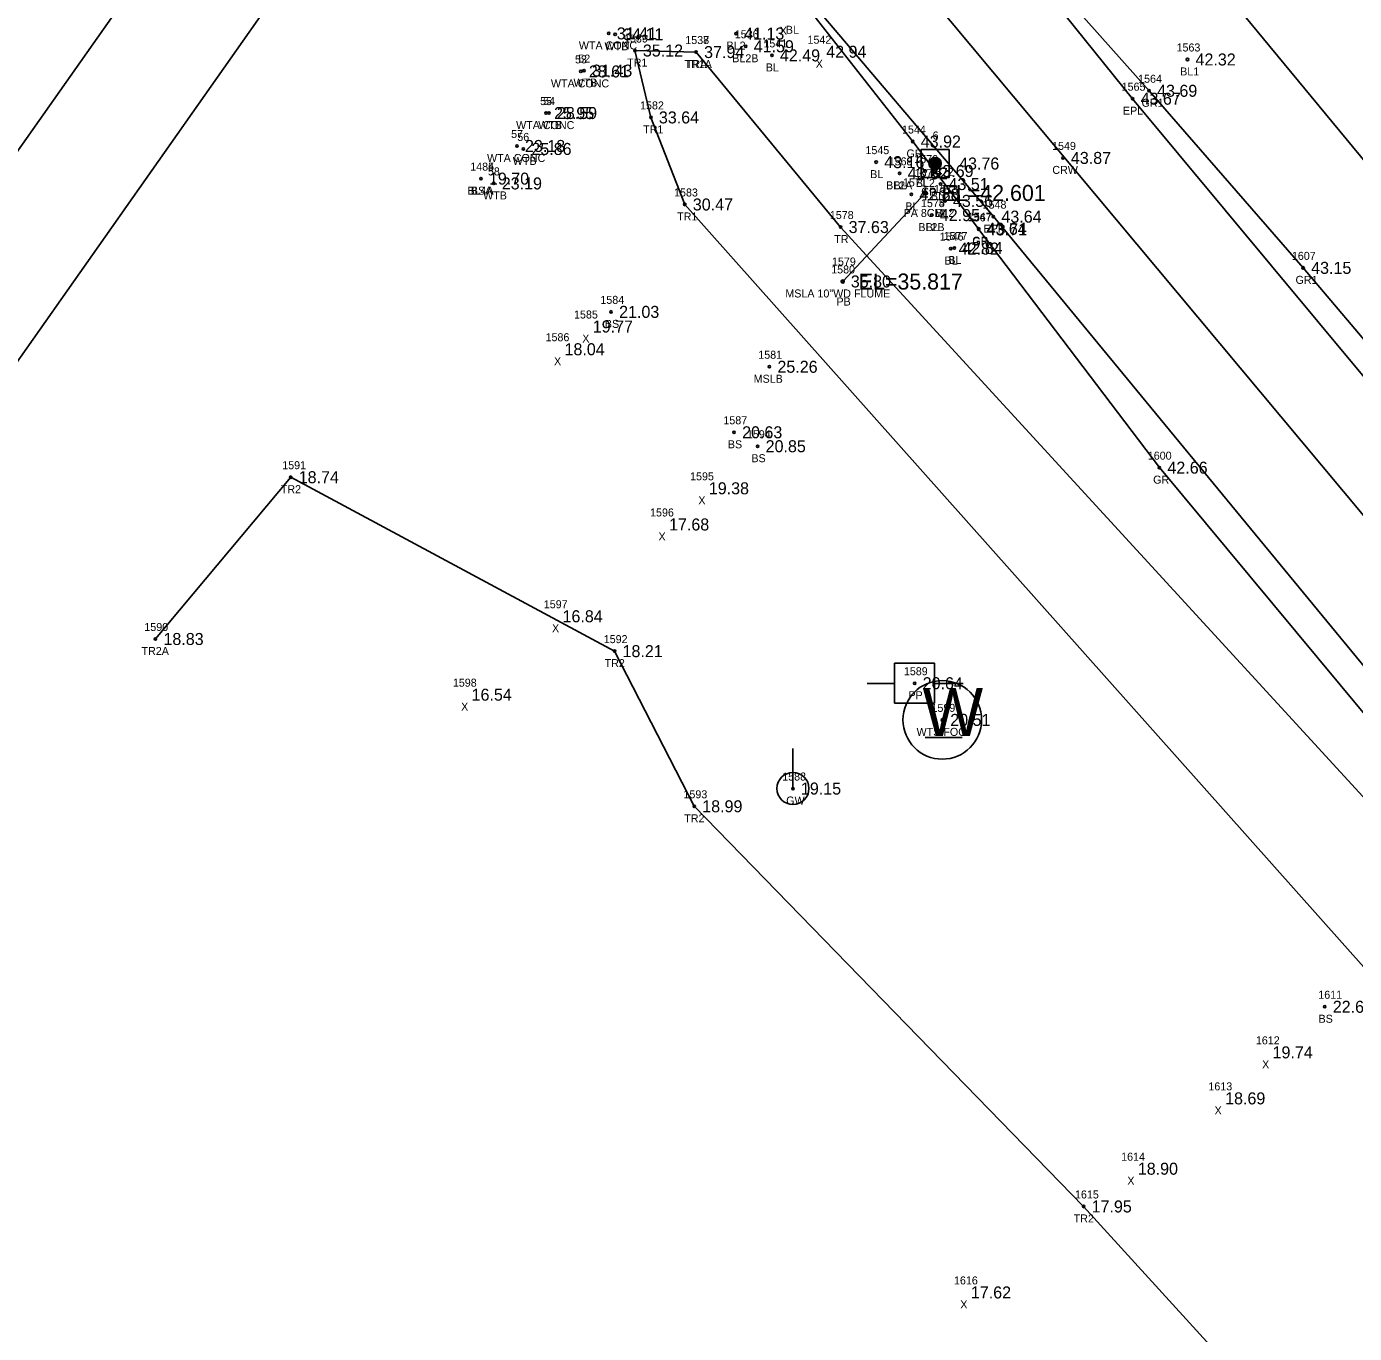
# Model space of a CAD drawing. Extents: x 2042117 to 2045853, y 303080 to 309569.
# Drawn here: x 2043426.9 to 2043592.8, y 305650.3 to 305813.6 of the extents above; entities that cross this region are included whole.
import ezdxf

# ---------------------------------------------------------------- set-up
doc = ezdxf.new("R2010")
doc.units = 0
for name, color, linetype in [('RD_DTM_BkLn_txCode', 7, 'Continuous'), ('RD_EX_DR_Pipe', 7, 'Continuous'), ('RD_EX_DR_Pipe_txCode', 7, 'Continuous'), ('RD_EX_GuardRail', 7, 'Continuous'), ('RD_EX_GuardRail_txCode', 7, 'Continuous'), ('RD_EX_Misc_txCode', 7, 'Continuous'), ('RD_EX_RailRoad', 7, 'Continuous'), ('RD_EX_Road', 7, 'Continuous'), ('RD_EX_Road_txCode', 7, 'Continuous'), ('RD_EX_TX_GuardRail_ELEV', 7, 'Continuous'), ('RD_EX_TX_Misc_ELEV', 7, 'Continuous'), ('RD_EX_TX_Road_ELEV', 7, 'Continuous'), ('RD_EX_TX_UT_ELEV', 7, 'Continuous'), ('RD_EX_TX_VEG_ELEV', 7, 'Continuous'), ('RD_EX_UT', 7, 'Continuous'), ('RD_EX_UT_txCode', 7, 'Continuous'), ('RD_EX_VEG', 7, 'Continuous'), ('RD_EX_VEG_txCode', 7, 'Continuous'), ('RD_HC_Cl', 7, 'Continuous'), ('RD_HC_Survey', 7, 'Continuous'), ('RD_HC_Survey_ELEV', 7, 'Continuous'), ('RD_HC_Survey_txCode', 7, 'Continuous'), ('RD_SMD_Locator', 7, 'Continuous'), ('RD_TX_Pipe_ElevEX', 7, 'Continuous')]:
    doc.layers.add(name, color=color, linetype=linetype)

msp = doc.modelspace()

# ---------------------------------------------------------------- linework, layer by layer
at = {"layer": 'RD_EX_DR_Pipe'}
msp.add_line((2043539.19, 305792.81), (2043528.84, 305781.74), dxfattribs=at)
at = {"layer": 'RD_EX_GuardRail'}
for points in [[(2043536.57, 305840.53), (2043552.74, 305821.73), (2043567.12, 305805.58), (2043586.37, 305783.45), (2043631.29, 305730.39), (2043695.95, 305653.5), (2043733.01, 305610.16)], [(2043521.57, 305819.7), (2043537.59, 305799.24), (2043545.81, 305788.34), (2043545.84, 305788.25), (2043568.41, 305758.48), (2043608.02, 305710.85), (2043672.21, 305633.93), (2043713.59, 305584.16)]]:
    msp.add_lwpolyline(points, dxfattribs=at)
at = {"layer": 'RD_EX_RailRoad'}
for points in [[(2043364.31, 305710.83), (2043487.58, 305885.88), (2043596.31, 306040.36)], [(2043376.84, 305702.3), (2043499.95, 305877.29), (2043608.72, 306031.56)]]:
    msp.add_lwpolyline(points, dxfattribs=at)
at = {"layer": 'RD_EX_Road'}
for points in [[(2043536.39, 305840.18), (2043565.06, 305804.59), (2043628.71, 305728.05), (2043693.07, 305651.37)], [(2043522.11, 305820), (2043547.67, 305789.85), (2043610.72, 305713.32), (2043674.95, 305636.32), (2043738.18, 305559.62), (2043802.42, 305482.71), (2043865.72, 305405.84), (2043929.53, 305328.85), (2043994.13, 305253.28), (2044057.4, 305176.5), (2044121.27, 305100.2), (2044185.29, 305023.54), (2044249.56, 304947.28), (2044313.31, 304870.31), (2044377.09, 304793.29), (2044442, 304716.26), (2044505.92, 304639.55), (2044570.44, 304562.35), (2044634.61, 304485.93), (2044698.46, 304409.27), (2044762.46, 304332.37)]]:
    msp.add_lwpolyline(points, dxfattribs=at)
at = {"layer": 'RD_EX_UT'}
for p, q in [((2043540.32, 305734.05), (2043535.32, 305734.05)), ((2043535.32, 305734.05), (2043535.32, 305729.05)), ((2043540.32, 305729.05), (2043540.32, 305734.05)), ((2043531.89, 305731.49), (2043535.36, 305731.49)), ((2043540.25, 305731.49), (2043543.89, 305731.49)), ((2043535.32, 305729.05), (2043540.32, 305729.05)), ((2043539.15, 305724.75), (2043543.78, 305724.75)), ((2043522.62, 305718.38), (2043522.62, 305723.38))]:
    msp.add_line(p, q, dxfattribs=at)
for centre, radius in [((2043541.28, 305726.96), 4.91), ((2043522.62, 305718.38), 2)]:
    msp.add_circle(centre, radius, dxfattribs=at)
at = {"layer": 'RD_EX_VEG'}
for points in [[(2043547.51, 305881.5), (2043539.7, 305861.32), (2043541.74, 305855.07), (2043567.73, 305828.7), (2043642.4, 305738.29), (2043706.88, 305661.84), (2043768.33, 305586.86), (2043834.29, 305506.38), (2043895.63, 305432.16), (2043964.52, 305353.99), (2044012.41, 305288.23), (2044020.96, 305286.08), (2044026.64, 305287.13), (2044039.88, 305282.36)], [(2043510.52, 305810.42), (2043502.87, 305810.61), (2043504.87, 305802.25), (2043509.11, 305791.37), (2043594.27, 305695.69), (2043658.16, 305620.89), (2043717.86, 305542.89), (2043784.35, 305466.31), (2043848.97, 305392.37), (2043916.01, 305316.79), (2043971.98, 305240.84)], [(2043510.52, 305810.42), (2043528.58, 305788.55), (2043603.52, 305706.8), (2043669.11, 305631.48), (2043746.08, 305529.27), (2043781.83, 305496.01), (2043793.11, 305482.33), (2043857.16, 305399.04), (2043922.61, 305323.93), (2043978.69, 305250.66), (2043978.39, 305246.16), (2043971.98, 305240.84)], [(2043442.97, 305737.07), (2043459.87, 305757.29), (2043500.33, 305735.55), (2043510.29, 305716.16), (2043558.94, 305666.15), (2043625.65, 305592.92), (2043688.91, 305518.94), (2043753.11, 305437.19), (2043818.03, 305364.7), (2043877.83, 305282.82), (2043938.63, 305211.62), (2044011.48, 305138.99), (2044075.86, 305057.44), (2044138.75, 304984.38), (2044203.27, 304905.13), (2044266.06, 304829.27), (2044328.58, 304748.23), (2044394.11, 304672.51), (2044456.79, 304595.02), (2044489.64, 304560.38)]]:
    msp.add_lwpolyline(points, dxfattribs=at)
at = {"layer": 'RD_HC_Cl'}
msp.add_line((2043284.3, 306123.24), (2045221.31, 303804), dxfattribs=at)
at = {"layer": 'RD_HC_Survey'}
for p, q in [((2043539.75, 305796.04), (2043539.75, 305796.94)), ((2043539.78, 305796.01), (2043539.78, 305796.97)), ((2043539.8, 305795.98), (2043539.8, 305797)), ((2043539.82, 305795.95), (2043539.82, 305797.03)), ((2043539.85, 305795.93), (2043539.85, 305797.05)), ((2043539.87, 305795.9), (2043539.87, 305797.07)), ((2043539.9, 305795.88), (2043539.9, 305797.09)), ((2043539.92, 305795.87), (2043539.92, 305797.11)), ((2043539.95, 305795.85), (2043539.95, 305797.13)), ((2043539.97, 305795.83), (2043539.97, 305797.15)), ((2043540, 305795.82), (2043540, 305797.16)), ((2043540.02, 305795.81), (2043540.02, 305797.17)), ((2043540.05, 305795.79), (2043540.05, 305797.19)), ((2043540.07, 305795.78), (2043540.07, 305797.2)), ((2043540.1, 305795.77), (2043540.1, 305797.21)), ((2043540.12, 305795.76), (2043540.12, 305797.22)), ((2043540.15, 305795.75), (2043540.15, 305797.22)), ((2043540.17, 305795.75), (2043540.17, 305797.23)), ((2043540.2, 305795.74), (2043540.2, 305797.24)), ((2043540.22, 305795.74), (2043540.22, 305797.24)), ((2043540.25, 305795.73), (2043540.25, 305797.25)), ((2043540.27, 305795.73), (2043540.27, 305797.25)), ((2043540.29, 305795.72), (2043540.29, 305797.25)), ((2043540.32, 305795.72), (2043540.32, 305797.26)), ((2043540.34, 305795.72), (2043540.34, 305797.26)), ((2043540.37, 305795.72), (2043540.37, 305797.26)), ((2043540.39, 305795.72), (2043540.39, 305797.26)), ((2043540.42, 305795.72), (2043540.42, 305797.26)), ((2043540.44, 305795.72), (2043540.44, 305797.26)), ((2043540.47, 305795.73), (2043540.47, 305797.25)), ((2043540.49, 305795.73), (2043540.49, 305797.25)), ((2043540.52, 305795.73), (2043540.52, 305797.25)), ((2043540.54, 305795.74), (2043540.54, 305797.24)), ((2043540.57, 305795.74), (2043540.57, 305797.23)), ((2043540.59, 305795.75), (2043540.59, 305797.23)), ((2043540.62, 305795.76), (2043540.62, 305797.22)), ((2043540.64, 305795.77), (2043540.64, 305797.21)), ((2043540.67, 305795.78), (2043540.67, 305797.2)), ((2043540.69, 305795.79), (2043540.69, 305797.19)), ((2043540.72, 305795.8), (2043540.72, 305797.18)), ((2043540.74, 305795.81), (2043540.74, 305797.17)), ((2043540.77, 305795.83), (2043540.77, 305797.15)), ((2043540.79, 305795.84), (2043540.79, 305797.14)), ((2043540.81, 305795.86), (2043540.81, 305797.12)), ((2043540.84, 305795.88), (2043540.84, 305797.1)), ((2043540.86, 305795.9), (2043540.86, 305797.08)), ((2043540.89, 305795.92), (2043540.89, 305797.06)), ((2043540.91, 305795.94), (2043540.91, 305797.04)), ((2043540.94, 305795.96), (2043540.94, 305797.01)), ((2043540.96, 305795.99), (2043540.96, 305796.99)), ((2043540.99, 305796.02), (2043540.99, 305796.95)), ((2043539.63, 305796.31), (2043539.63, 305796.67)), ((2043539.65, 305796.23), (2043539.65, 305796.75)), ((2043539.68, 305796.17), (2043539.68, 305796.81)), ((2043539.7, 305796.12), (2043539.7, 305796.86)), ((2043539.73, 305796.08), (2043539.73, 305796.9)), ((2043541.01, 305796.06), (2043541.01, 305796.92)), ((2043541.04, 305796.1), (2043541.04, 305796.88)), ((2043541.06, 305796.14), (2043541.06, 305796.84)), ((2043541.09, 305796.2), (2043541.09, 305796.78)), ((2043541.11, 305796.27), (2043541.11, 305796.71)), ((2043541.14, 305796.38), (2043541.14, 305796.6))]:
    msp.add_line(p, q, dxfattribs=at)
msp.add_lwpolyline([(2043542.12, 305798.24), (2043538.63, 305798.24), (2043538.63, 305794.74), (2043542.12, 305794.74)], close=True, dxfattribs=at)
msp.add_circle((2043540.38, 305796.49), 0.769, dxfattribs=at)
at = {"layer": 'RD_SMD_Locator'}
for centre, radius in [((2043499.61, 305812.75), 0.15), ((2043500.41, 305812.63), 0.15), ((2043515.52, 305812.73), 0.15), ((2043502.87, 305810.61), 0.15), ((2043510.52, 305810.42), 0.15), ((2043510.52, 305810.42), 0.15), ((2043516.72, 305811.14), 0.15), ((2043519.99, 305810), 0.15), ((2043571.92, 305809.49), 0.15), ((2043496.12, 305808), 0.15), ((2043496.53, 305808.1), 0.15), ((2043567.12, 305805.58), 0.15), ((2043565.06, 305804.59), 0.15), ((2043491.77, 305802.79), 0.15), ((2043492.13, 305802.8), 0.15), ((2043504.87, 305802.25), 0.15), ((2043488.14, 305798.68), 0.15), ((2043537.59, 305799.24), 0.15), ((2043488.94, 305798.31), 0.15), ((2043556.35, 305797.19), 0.15), ((2043533.02, 305796.66), 0.15), ((2043535.95, 305795.26), 0.15), ((2043535.95, 305795.26), 0.15), ((2043539.17, 305795.55), 0.15), ((2043540.38, 305796.49), 0.15), ((2043483.64, 305794.6), 0.15), ((2043483.64, 305794.6), 0.15), ((2043485.24, 305794), 0.15), ((2043541.06, 305793.92), 0.15), ((2043537.42, 305792.63), 0.15), ((2043539.19, 305792.81), 0.2), ((2043541.61, 305791.82), 0.15), ((2043509.11, 305791.37), 0.15), ((2043528.58, 305788.55), 0.15), ((2043539.97, 305790.04), 0.15), ((2043539.97, 305790.04), 0.15), ((2043547.67, 305789.85), 0.15), ((2043545.81, 305788.34), 0.15), ((2043545.84, 305788.25), 0.15), ((2043542.33, 305785.86), 0.15), ((2043542.8, 305785.93), 0.15), ((2043586.37, 305783.45), 0.15), ((2043528.84, 305781.74), 0.2), ((2043528.85, 305781.75), 0.15), ((2043499.9, 305777.95), 0.15), ((2043519.68, 305771.09), 0.15), ((2043515.27, 305762.9), 0.15), ((2043518.21, 305761.16), 0.15), ((2043459.87, 305757.29), 0.15), ((2043568.41, 305758.48), 0.15), ((2043442.97, 305737.07), 0.15), ((2043500.33, 305735.55), 0.15), ((2043537.83, 305731.54), 0.15), ((2043541.28, 305726.96), 0.15), ((2043522.62, 305718.38), 0.15), ((2043510.29, 305716.16), 0.15), ((2043589.07, 305691.11), 0.15), ((2043558.94, 305666.15), 0.15)]:
    msp.add_circle(centre, radius, dxfattribs=at)

# ---------------------------------------------------------------- texts
at = {"layer": 'RD_DTM_BkLn_txCode'}
for s, p in [('BL', (2043521.73, 305812.7)), ('1536', (2043515.35, 305812.14)), ('1541', (2043518.93, 305811)), ('BL2', (2043514.32, 305810.73)), ('1563', (2043570.55, 305810.49)), ('BL2B', (2043515.04, 305809.14)), ('BL', (2043519.23, 305808)), ('BL1', (2043571, 305807.49)), ('1545', (2043531.68, 305797.66)), ('1568', (2043534.58, 305796.26)), ('1569', (2043534.58, 305796.26)), ('1570', (2043537.78, 305796.55)), ('1484', (2043482.3, 305795.6)), ('1485', (2043482.3, 305795.6)), ('BL', (2043532.27, 305794.66)), ('1572', (2043539.71, 305794.92)), ('BSA', (2043482.38, 305792.6)), ('BL2A', (2043534.26, 305793.26)), ('BL', (2043535.2, 305793.26)), ('1571', (2043536.36, 305793.63)), ('BL2', (2043537.97, 305793.55)), ('1573', (2043540.26, 305792.82)), ('BL4A', (2043481.95, 305792.6)), ('1574', (2043538.62, 305791.04)), ('1575', (2043538.62, 305791.04)), ('BL2', (2043539.85, 305791.92)), ('BL', (2043536.67, 305790.63)), ('BL2', (2043540.4, 305789.82)), ('BL2B', (2043538.29, 305788.04)), ('BL', (2043539.22, 305788.04)), ('1546', (2043540.96, 305786.86)), ('1577', (2043541.45, 305786.93)), ('BL', (2043541.57, 305783.86)), ('BL', (2043542.04, 305783.93)), ('1584', (2043498.56, 305778.95)), ('BS', (2043499.12, 305775.95)), ('1587', (2043513.93, 305763.9)), ('1594', (2043516.87, 305762.16)), ('BS', (2043514.49, 305760.9)), ('BS', (2043517.43, 305759.16)), ('1611', (2043588.26, 305692.11)), ('BS', (2043588.29, 305689.11))]:
    msp.add_text(s, height=1, dxfattribs=at).set_placement(p)
at = {"layer": 'RD_EX_DR_Pipe_txCode'}
for s, p in [('1576', (2043537.82, 305794.81)), ('PA 8CM', (2043536.45, 305789.81)), ('1579', (2043527.5, 305783.74)), ('PB', (2043528.06, 305778.74))]:
    msp.add_text(s, height=1, dxfattribs=at).set_placement(p)
at = {"layer": 'RD_EX_GuardRail_txCode'}
for s, p in [('1564', (2043565.75, 305806.58)), ('GR1', (2043566.18, 305803.58)), ('1544', (2043536.25, 305800.24)), ('GR', (2043536.81, 305797.24)), ('1547', (2043544.47, 305789.34)), ('1567', (2043544.47, 305789.25)), ('GR', (2043545.03, 305786.34)), ('GR', (2043545.06, 305786.25)), ('1607', (2043584.96, 305784.45)), ('GR1', (2043585.42, 305781.45)), ('1600', (2043566.96, 305759.48)), ('GR', (2043567.63, 305756.48))]:
    msp.add_text(s, height=1, dxfattribs=at).set_placement(p)
at = {"layer": 'RD_EX_Misc_txCode'}
for s, p in [('X', (2043520.98, 305812.59)), ('1542', (2043524.44, 305811.46)), ('WTA CONC', (2043495.87, 305810.75)), ('WTB', (2043499.08, 305810.63)), ('53', (2043495.39, 305809)), ('52', (2043495.8, 305809.1)), ('X', (2043525.47, 305808.46)), ('WTA CONC', (2043492.38, 305806)), ('WTB', (2043495.2, 305806.1)), ('55', (2043491.03, 305803.79)), ('54', (2043491.4, 305803.8)), ('57', (2043487.41, 305799.68)), ('WTA CONC', (2043488.03, 305800.79)), ('56', (2043488.18, 305799.31)), ('WTB', (2043490.8, 305800.8)), ('WTA CONC', (2043484.4, 305796.68)), ('WTB', (2043487.61, 305796.31)), ('58', (2043484.51, 305795)), ('WTB', (2043483.91, 305792)), ('1580', (2043527.4, 305782.75)), ('MSLA 10"WD FLUME', (2043521.67, 305779.75)), ('1585', (2043495.27, 305777.12)), ('1586', (2043491.71, 305774.28)), ('X', (2043496.3, 305774.12)), ('X', (2043492.77, 305771.28)), ('1581', (2043518.29, 305772.09)), ('MSLB', (2043517.71, 305769.09)), ('1595', (2043509.77, 305756.9)), ('X', (2043510.8, 305753.9)), ('1596', (2043504.77, 305752.38)), ('X', (2043505.82, 305749.38)), ('1597', (2043491.49, 305740.91)), ('X', (2043492.52, 305737.91)), ('1598', (2043480.13, 305731.11)), ('X', (2043481.16, 305728.11)), ('1612', (2043580.46, 305686.41)), ('X', (2043581.24, 305683.41)), ('1613', (2043574.53, 305680.66)), ('X', (2043575.3, 305677.66)), ('1614', (2043563.63, 305671.87)), ('X', (2043564.4, 305668.87)), ('1616', (2043542.74, 305656.41)), ('X', (2043543.53, 305653.41))]:
    msp.add_text(s, height=1, dxfattribs=at).set_placement(p)
at = {"layer": 'RD_EX_Road_txCode'}
for s, p in [('1565', (2043563.69, 305805.59)), ('EPL', (2043563.85, 305802.59)), ('1548', (2043546.32, 305790.85)), ('EPR', (2043546.44, 305787.85))]:
    msp.add_text(s, height=1, dxfattribs=at).set_placement(p)
at = {"layer": 'RD_EX_TX_GuardRail_ELEV'}
for s, p in [('43.69', (2043568.12, 305804.83)), ('43.92', (2043538.59, 305798.49)), ('43.64', (2043546.81, 305787.59)), ('43.71', (2043546.84, 305787.5)), ('43.15', (2043587.37, 305782.7)), ('42.66', (2043569.41, 305757.73))]:
    msp.add_text(s, height=1.5, dxfattribs=at).set_placement(p)
at = {"layer": 'RD_EX_TX_Misc_ELEV'}
for s, p in [('31.41', (2043500.61, 305812)), ('34.11', (2043501.41, 305811.88)), ('41.13', (2043516.52, 305811.98)), ('41.59', (2043517.72, 305810.39)), ('42.49', (2043520.99, 305809.25)), ('42.94', (2043526.78, 305809.71)), ('42.32', (2043572.92, 305808.74)), ('28.61', (2043497.12, 305807.25)), ('31.43', (2043497.53, 305807.35)), ('25.95', (2043492.77, 305802.04)), ('28.59', (2043493.13, 305802.05)), ('23.18', (2043489.14, 305797.93)), ('25.86', (2043489.94, 305797.56)), ('43.16', (2043534.02, 305795.91)), ('19.70', (2043484.64, 305793.85)), ('19.70', (2043484.64, 305793.85)), ('43.62', (2043536.95, 305794.51)), ('43.62', (2043536.95, 305794.51)), ('43.69', (2043540.17, 305794.8)), ('23.19', (2043486.24, 305793.25)), ('43.51', (2043542.06, 305793.17)), ('42.88', (2043538.42, 305791.88)), ('43.56', (2043542.61, 305791.07)), ('42.95', (2043540.97, 305789.29)), ('42.95', (2043540.97, 305789.29)), ('42.82', (2043543.33, 305785.11)), ('42.84', (2043543.8, 305785.18)), ('35.80', (2043529.85, 305781)), ('21.03', (2043500.9, 305777.2)), ('19.77', (2043497.61, 305775.37)), ('18.04', (2043494.08, 305772.53)), ('25.26', (2043520.68, 305770.34)), ('20.63', (2043516.27, 305762.15)), ('20.85', (2043519.21, 305760.41)), ('19.38', (2043512.11, 305755.15)), ('17.68', (2043507.14, 305750.63)), ('16.84', (2043493.83, 305739.16)), ('16.54', (2043482.47, 305729.36)), ('22.64', (2043590.07, 305690.36)), ('19.74', (2043582.55, 305684.66)), ('18.69', (2043576.62, 305678.91)), ('18.90', (2043565.71, 305670.12)), ('17.62', (2043544.85, 305654.66))]:
    msp.add_text(s, height=1.5, dxfattribs=at).set_placement(p)
at = {"layer": 'RD_EX_TX_Road_ELEV'}
for s, p in [('43.67', (2043566.06, 305803.84)), ('43.64', (2043548.67, 305789.1))]:
    msp.add_text(s, height=1.5, dxfattribs=at).set_placement(p)
at = {"layer": 'RD_EX_TX_UT_ELEV'}
for s, p in [('20.51', (2043542.28, 305726.21)), ('19.15', (2043523.62, 305717.63))]:
    msp.add_text(s, height=1.5, dxfattribs=at).set_placement(p)
at = {"layer": 'RD_EX_TX_VEG_ELEV'}
for s, p in [('35.12', (2043503.87, 305809.86)), ('37.94', (2043511.52, 305809.67)), ('37.94', (2043511.52, 305809.67)), ('33.64', (2043505.87, 305801.5)), ('30.47', (2043510.11, 305790.62)), ('37.63', (2043529.58, 305787.8)), ('18.74', (2043460.87, 305756.54)), ('18.83', (2043443.97, 305736.32)), ('18.21', (2043501.33, 305734.8)), ('18.99', (2043511.29, 305715.41)), ('17.95', (2043559.94, 305665.4))]:
    msp.add_text(s, height=1.5, dxfattribs=at).set_placement(p)
at = {"layer": 'RD_EX_UT'}
msp.add_text('W', height=6, dxfattribs=at).set_placement((2043538.81, 305724.96))
at = {"layer": 'RD_EX_UT_txCode'}
for s, p in [('1589', (2043536.48, 305732.54)), ('PP', (2043537.05, 305729.54)), ('1599', (2043539.93, 305727.96)), ('WTS FOC', (2043538.07, 305724.96)), ('1588', (2043521.28, 305719.38)), ('GW', (2043521.78, 305716.38))]:
    msp.add_text(s, height=1, dxfattribs=at).set_placement(p)
at = {"layer": 'RD_EX_VEG_txCode'}
for s, p in [('1539', (2043501.52, 305811.61)), ('1537', (2043509.17, 305811.42)), ('1538', (2043509.17, 305811.42)), ('TR1', (2043501.91, 305808.61)), ('TR1A', (2043509.07, 305808.42)), ('TRA', (2043509.23, 305808.42)), ('1582', (2043503.52, 305803.25)), ('TR1', (2043503.91, 305800.25)), ('1583', (2043507.77, 305792.37)), ('TR1', (2043508.15, 305789.37)), ('1578', (2043527.23, 305789.55)), ('TR', (2043527.78, 305786.55)), ('1591', (2043458.81, 305758.29)), ('TR2', (2043458.63, 305755.29)), ('1590', (2043441.58, 305738.07)), ('1592', (2043498.98, 305736.55)), ('TR2A', (2043441.23, 305735.07)), ('TR2', (2043499.09, 305733.55)), ('1593', (2043508.94, 305717.16)), ('TR2', (2043509.04, 305714.16)), ('1615', (2043557.86, 305667.15)), ('TR2', (2043557.7, 305664.15))]:
    msp.add_text(s, height=1, dxfattribs=at).set_placement(p)
at = {"layer": 'RD_HC_Survey_ELEV'}
for s, p in [('43.76', (2043543.38, 305795.74)), ('43.87', (2043557.35, 305796.44)), ('20.64', (2043538.83, 305730.79))]:
    msp.add_text(s, height=1.5, dxfattribs=at).set_placement(p)
at = {"layer": 'RD_HC_Survey_txCode'}
for s, p in [('6', (2043540.07, 305799.49)), ('1549', (2043555, 305798.19)), ('CRW', (2043555.03, 305795.19)), ('CP 6', (2043538.65, 305792.49))]:
    msp.add_text(s, height=1, dxfattribs=at).set_placement(p)
at = {"layer": 'RD_TX_Pipe_ElevEX'}
for s, p in [('EL=42.601', (2043541.19, 305791.81)), ('EL=35.817', (2043530.84, 305780.74))]:
    msp.add_text(s, height=2, dxfattribs=at).set_placement(p)

doc.saveas('drawing.dxf')
